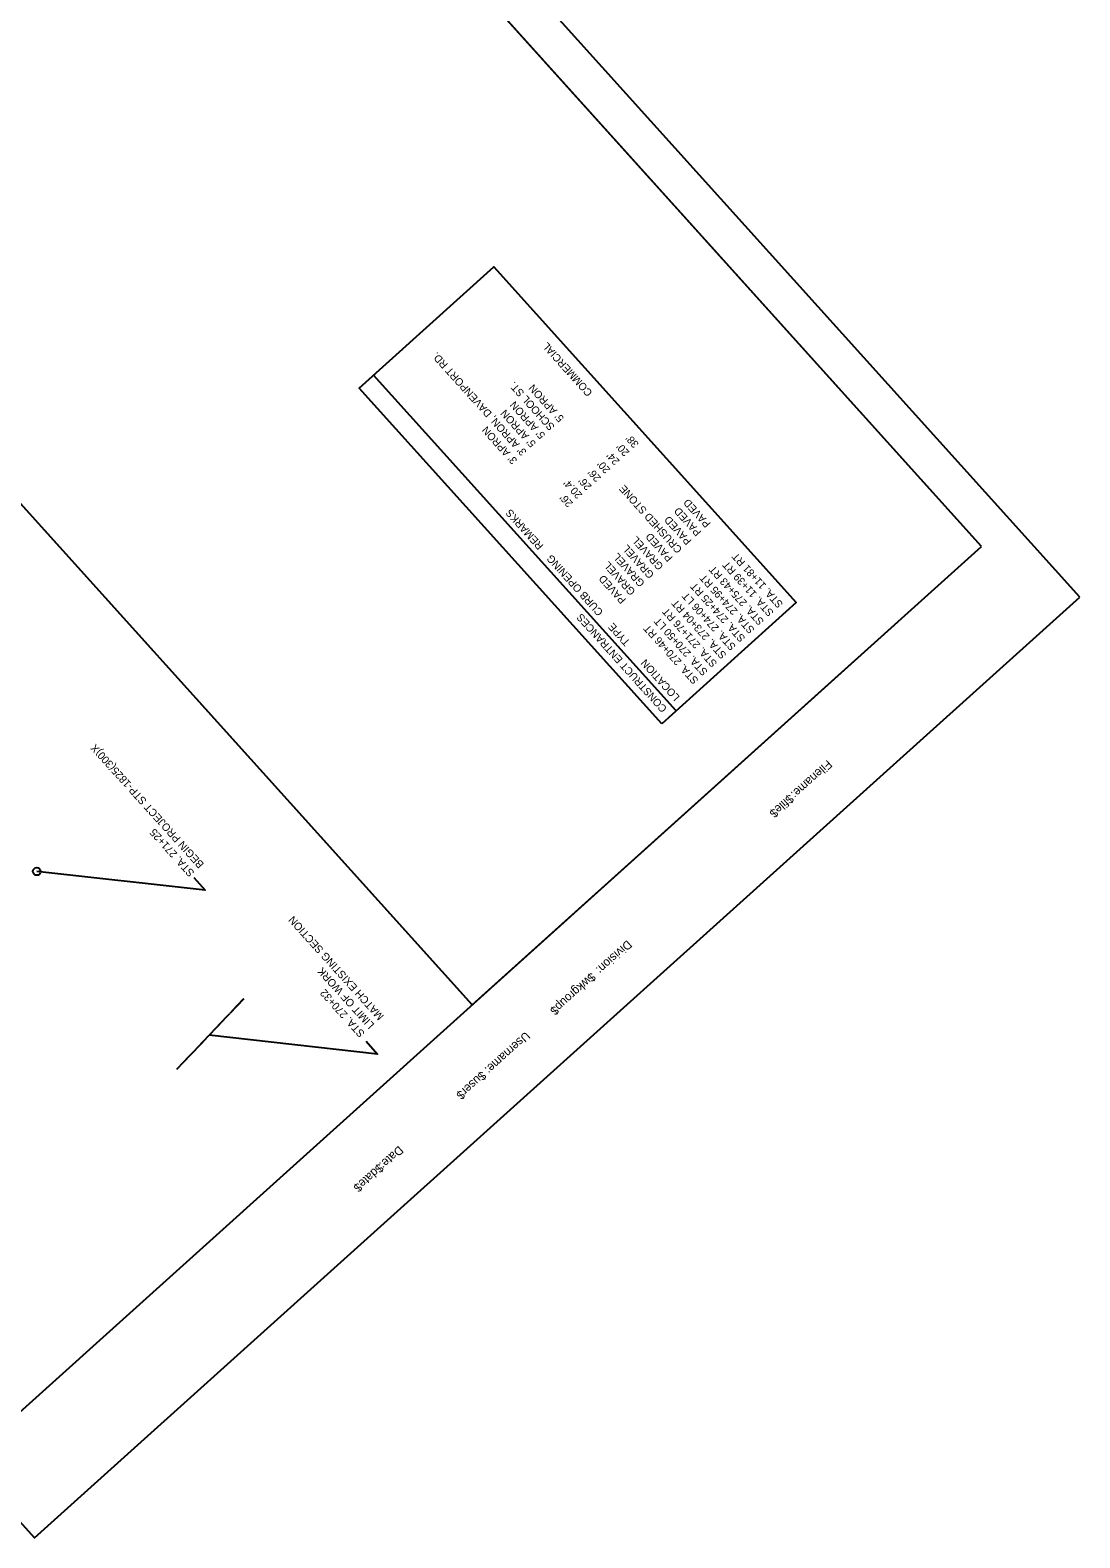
# Model space of a CAD drawing. Extents: x 1111534 to 1112511, y 616515 to 617514.
# Drawn here: x 1112101 to 1112511, y 616515 to 617105 of the extents above; entities that cross this region are included whole.
import ezdxf

# ---------------------------------------------------------------- set-up
doc = ezdxf.new("R2010")
doc.units = 0
for name, color, linetype in [('ANNOTATION', 7, 'Continuous'), ('BORDER', 7, 'Continuous'), ('CLIPS', 7, 'Continuous'), ('D_Roadway_Centerline_Flags', 7, 'Continuous'), ('PLOT BOUNDARY', 7, 'Continuous')]:
    doc.layers.add(name, color=color, linetype=linetype)

msp = doc.modelspace()

# ---------------------------------------------------------------- linework, layer by layer
at = {"layer": 'ANNOTATION'}
for p, q in [((1112353.11, 616838.22), (1112234.85, 616969.56)), ((1112184.08, 616725.52), (1112178.62, 616719.78)), ((1112179.59, 616720.79), (1112184.01, 616725.44)), ((1112175.96, 616716.98), (1112170.51, 616711.24)), ((1112174.21, 616715.13), (1112178.62, 616719.78)), ((1112166.09, 616706.6), (1112170.51, 616711.24)), ((1112163.24, 616703.6), (1112157.78, 616697.86)), ((1112168, 616708.6), (1112162.54, 616702.87)), ((1112158.12, 616698.22), (1112162.54, 616702.87))]:
    msp.add_line(p, q, dxfattribs=at)
msp.add_lwpolyline([(1112347.48, 616833.15), (1112229.22, 616964.49), (1112281.85, 617011.88), (1112400.11, 616880.54)], close=True, dxfattribs=at)
for points in [[(1112164.48, 616772.97), (1112168.98, 616767.98), (1112103.11, 616775.33)], [(1112231.88, 616708.89), (1112236.38, 616703.89), (1112170.51, 616711.24)]]:
    msp.add_lwpolyline(points, dxfattribs=at)
at = {"layer": 'BORDER'}
for p, q in [((1112472.55, 616902.44), (1111937.25, 617496.96)), ((1112273.39, 616723.12), (1111771.54, 617280.48)), ((1112082.4, 616551.15), (1112472.55, 616902.44))]:
    msp.add_line(p, q, dxfattribs=at)
at = {"layer": 'CLIPS'}
msp.add_lwpolyline([(1112472.55, 616902.44), (1111970.7, 617459.8), (1111771.54, 617280.48), (1112273.39, 616723.12)], close=True, dxfattribs=at)
at = {"layer": 'D_Roadway_Centerline_Flags'}
msp.add_circle((1112103.11, 616775.33), 1.5, dxfattribs=at)
at = {"layer": 'PLOT BOUNDARY'}
msp.add_lwpolyline([(1112510.99, 616882.61), (1111942.23, 617514.28), (1111533.5, 617146.26), (1112102.26, 616514.59)], close=True, dxfattribs=at)

# ---------------------------------------------------------------- texts
at = {"layer": 'ANNOTATION'}
for s, height, rotation, p in [('COMMERCIAL', 2.953, 132, (1112320.62, 616962.82)), ("3' APRON, DAVENPORT RD.", 2.9531, 132, (1112294.85, 616939.63)), ('SCHOOL ST.', 2.953, 132, (1112305.84, 616949.51)), ("5' APRON ", 2.953, 132, (1112309.49, 616952.8)), ("5' APRON ", 2.953, 132, (1112302.17, 616946.21)), ("5' APRON ", 2.953, 132, (1112298.51, 616942.92)), ("3' APRON ", 2.953, 132, (1112291.2, 616936.33)), ("38'", 2.953, 132, (1112338.74, 616942.7)), ("20'", 2.953, 132, (1112335.08, 616939.41)), ("20'", 2.953, 132, (1112327.61, 616932.67)), ("24'", 2.953, 132, (1112331.26, 616935.97)), ("20.4'", 2.953, 132, (1112316.63, 616922.79)), ("26'", 2.953, 132, (1112320.29, 616926.09)), ("26'", 2.953, 132, (1112323.96, 616929.39)), ("26'", 2.953, 132, (1112312.98, 616919.5)), ('CRUSHED STONE', 2.9531, 132, (1112355.7, 616901.47)), ('LOCATION        TYPE     CURB OPENING    REMARKS', 2.9531, 132, (1112354.75, 616843.68)), ('PAVED', 2.953, 132, (1112363.18, 616908.2)), ('PAVED', 2.953, 132, (1112366.83, 616911.5)), ('PAVED', 2.953, 132, (1112359.36, 616904.77)), ('GRAVEL', 2.953, 132, (1112348.38, 616894.89)), ('PAVED', 2.953, 132, (1112352.05, 616898.19)), ('GRAVEL', 2.953, 132, (1112341.07, 616888.3)), ('GRAVEL', 2.953, 132, (1112344.73, 616891.59)), ('STA. 11+81 RT', 2.9531, 132, (1112395.15, 616880.05)), ('GRAVEL', 2.953, 132, (1112337.41, 616885.01)), ('STA. 275+43 RT', 2.9531, 132, (1112387.67, 616873.32)), ('STA. 11+39 RT', 2.9531, 132, (1112391.49, 616876.75)), ('PAVED', 2.953, 132, (1112333.75, 616881.71)), ('STA. 274+25 RT', 2.9531, 132, (1112380.37, 616866.74)), ('STA. 274+95 RT', 2.9531, 132, (1112384.02, 616870.02)), ('STA. 273+04 RT', 2.9531, 132, (1112373.04, 616860.14)), ('STA. 274+06 LT', 2.9531, 132, (1112376.7, 616863.44)), ('CONSTRUCT ENTRANCES', 2.9531, 132, (1112349.76, 616839.18)), ('STA. 270+50 LT', 2.9531, 132, (1112365.73, 616853.56)), ('STA. 271+76 RT', 2.9531, 132, (1112369.39, 616856.85)), ('STA. 270+46 RT', 2.9531, 132, (1112362.07, 616850.26)), ('BEGIN PROJECT STP-1825(300)X', 3, 132.0586, (1112168.7, 616778.28)), ('STA. 271+25', 3, 132.0586, (1112164.99, 616774.93)), ('MATCH EXISTING SECTION', 3, 132.0586, (1112239.03, 616718.78)), ('LIMIT OF WORK', 3, 132.0586, (1112235.32, 616715.43)), ('STA. 270+32', 3, 132.0586, (1112231.6, 616712.08))]:
    msp.add_text(s, height=height, rotation=rotation, dxfattribs=at).set_placement(p)
at = {"layer": 'BORDER'}
for s, p in [('Filename:', (1112412.31, 616819.17)), ('$file$', (1112397.34, 616805.7)), ('Division:', (1112334.02, 616748.68)), ('$wkgroup$', (1112319.89, 616735.96)), ('Username:', (1112294.26, 616712.88)), ('$user$', (1112277.08, 616697.41)), ('Date:', (1112244.66, 616668.22)), ('$date$', (1112236.9, 616661.23))]:
    msp.add_text(s, height=3.348, rotation=222, dxfattribs=at).set_placement(p)

doc.saveas('drawing.dxf')
